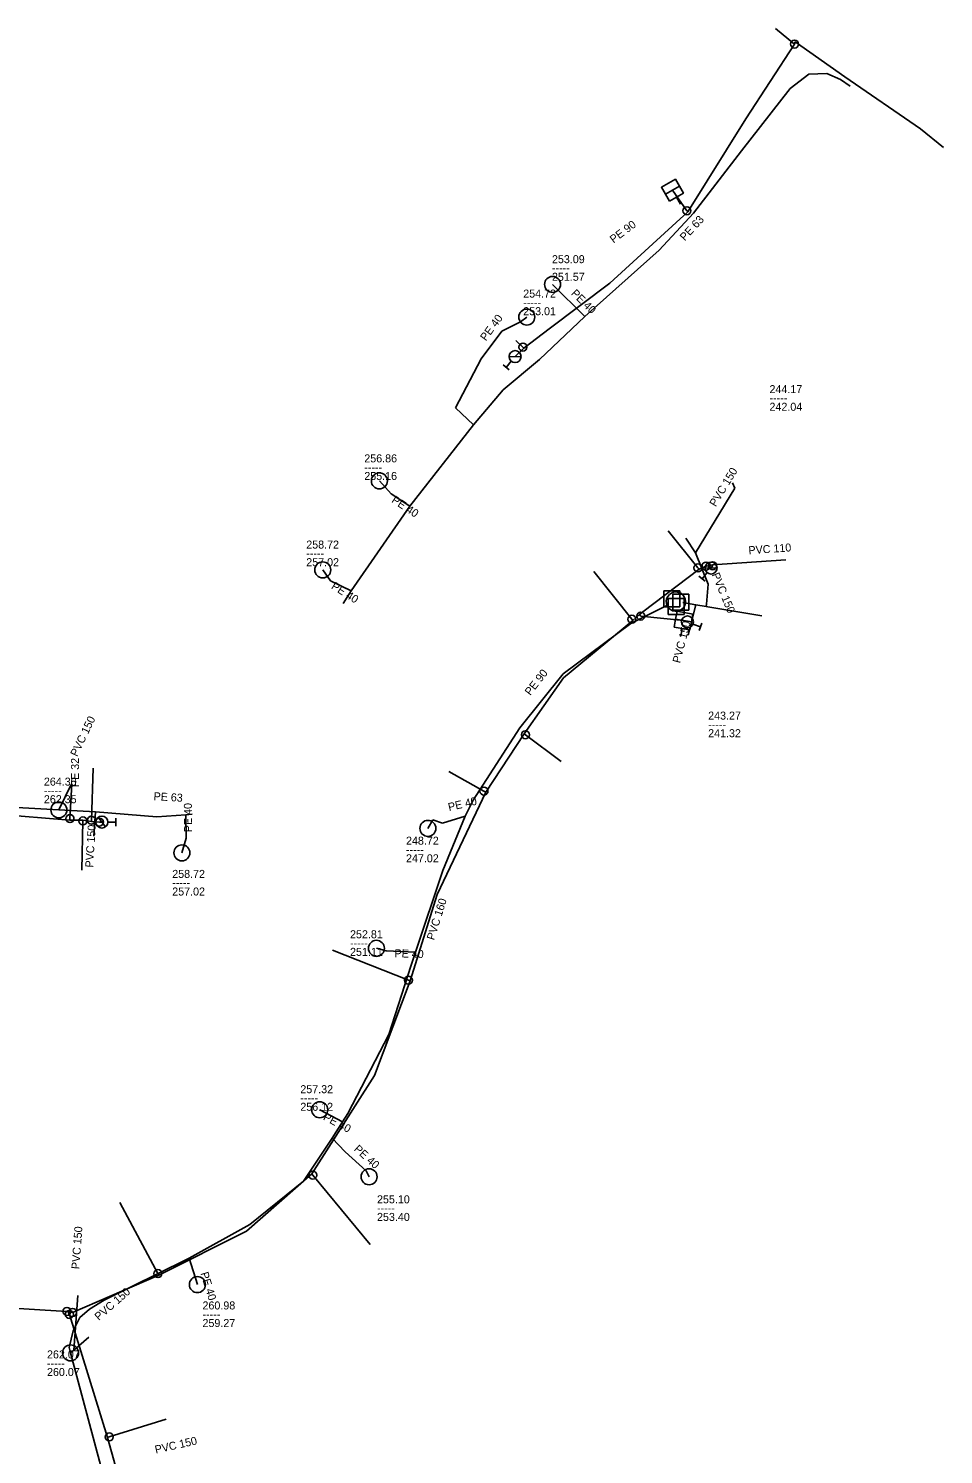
# Model space of a CAD drawing. Extents: x -770828 to -770111, y -1050344 to -1049447.
# Drawn here: x -770489.8 to -770375.5, y -1049916.1 to -1049737.9 of the extents above; entities that cross this region are included whole.
import ezdxf

# ---------------------------------------------------------------- set-up
doc = ezdxf.new("R2010")
doc.units = 0
doc.layers.add('Level 0', color=7, linetype='Continuous')

msp = doc.modelspace()

# ---------------------------------------------------------------- linework, layer by layer
at = {"layer": 'Level 0'}
for p, q in [((-770394.14, -1049739.85), (-770396.52, -1049737.91)), ((-770394.06, -1049739.59), (-770394.14, -1049739.85)), ((-770387.88, -1049743.95), (-770394.06, -1049739.59)), ((-770394.14, -1049739.85), (-770400.21, -1049749.18)), ((-770394.67, -1049745.42), (-770392.36, -1049743.62)), ((-770392.36, -1049743.62), (-770390.11, -1049743.54)), ((-770390.11, -1049743.54), (-770388.42, -1049744.28)), ((-770388.42, -1049744.28), (-770387.18, -1049745.13)), ((-770378.39, -1049750.44), (-770387.88, -1049743.95)), ((-770400.76, -1049753.2), (-770394.67, -1049745.42)), ((-770400.21, -1049749.18), (-770407.46, -1049760.81)), ((-770375.54, -1049752.77), (-770378.39, -1049750.44)), ((-770406.77, -1049760.98), (-770400.76, -1049753.2)), ((-770407.59, -1049760.68), (-770409.39, -1049758.11)), ((-770408.39, -1049759.84), (-770408.89, -1049758.98)), ((-770407.46, -1049760.81), (-770417.2, -1049769.74)), ((-770411.04, -1049765.6), (-770406.77, -1049760.98)), ((-770407.46, -1049760.81), (-770407.59, -1049760.68)), ((-770420.32, -1049773.89), (-770411.04, -1049765.6)), ((-770417.2, -1049769.74), (-770424.81, -1049775.44)), ((-770424.37, -1049769.88), (-770420.32, -1049773.89)), ((-770430.72, -1049775.71), (-770428.36, -1049774.58)), ((-770428.36, -1049774.58), (-770427.58, -1049773.96)), ((-770426.01, -1049779.27), (-770420.32, -1049773.89)), ((-770433.3, -1049779.19), (-770430.72, -1049775.71)), ((-770428.07, -1049777.72), (-770428.97, -1049776.89)), ((-770424.81, -1049775.44), (-770427.94, -1049777.86)), ((-770428.29, -1049778.93), (-770429.79, -1049778.88)), ((-770427.94, -1049777.86), (-770429.04, -1049778.91)), ((-770427.94, -1049777.86), (-770428.07, -1049777.72)), ((-770436.48, -1049785.3), (-770433.3, -1049779.19)), ((-770429.78, -1049780.57), (-770430.55, -1049779.93)), ((-770430.52, -1049783.05), (-770426.01, -1049779.27)), ((-770429.52, -1049779.48), (-770430.16, -1049780.25)), ((-770434.26, -1049787.42), (-770430.52, -1049783.05)), ((-770434.26, -1049787.42), (-770436.48, -1049785.3)), ((-770442.2, -1049797.59), (-770434.26, -1049787.42)), ((-770446, -1049794.44), (-770444.53, -1049796.05)), ((-770401.89, -1049794.68), (-770401.6, -1049795.33)), ((-770444.53, -1049796.05), (-770442.2, -1049797.59)), ((-770401.6, -1049795.33), (-770406.51, -1049803.42)), ((-770449.51, -1049808.19), (-770442.2, -1049797.59)), ((-770406.2, -1049805.3), (-770409.92, -1049800.66)), ((-770407.72, -1049801.61), (-770406.51, -1049803.42)), ((-770406.51, -1049803.42), (-770404.93, -1049807.33)), ((-770452.12, -1049806.93), (-770453.07, -1049805.56)), ((-770413.08, -1049810.8), (-770406.07, -1049805.46)), ((-770406.07, -1049805.46), (-770406.2, -1049805.3)), ((-770406.07, -1049805.46), (-770405.2, -1049805.08)), ((-770403.82, -1049805.34), (-770405.32, -1049805.29)), ((-770405.2, -1049805.08), (-770404.37, -1049804.93)), ((-770404.57, -1049805.32), (-770404.37, -1049805.03)), ((-770404.37, -1049804.93), (-770395.21, -1049804.29)), ((-770404.37, -1049805.03), (-770404.37, -1049804.93)), ((-770449.51, -1049808.19), (-770452.12, -1049806.93)), ((-770414.46, -1049811.72), (-770419.21, -1049805.74)), ((-770405.31, -1049806.98), (-770406.08, -1049806.34)), ((-770405.05, -1049805.89), (-770405.69, -1049806.66)), ((-770404.93, -1049807.33), (-770405.12, -1049809.84)), ((-770450.52, -1049809.77), (-770449.51, -1049808.19)), ((-770408.47, -1049808.17), (-770410.47, -1049808.17)), ((-770410.47, -1049808.17), (-770410.47, -1049810.17)), ((-770410.12, -1049809.15), (-770410.17, -1049809.45)), ((-770409.98, -1049808.87), (-770410.12, -1049809.15)), ((-770409.78, -1049808.63), (-770409.98, -1049808.87)), ((-770407.91, -1049809.14), (-770409.91, -1049809.14)), ((-770409.91, -1049809.14), (-770409.91, -1049811.14)), ((-770409.53, -1049808.45), (-770409.78, -1049808.63)), ((-770409.24, -1049808.34), (-770409.53, -1049808.45)), ((-770407.33, -1049808.57), (-770409.33, -1049808.57)), ((-770409.33, -1049808.57), (-770409.33, -1049810.57)), ((-770408.93, -1049808.31), (-770409.24, -1049808.34)), ((-770408.62, -1049808.36), (-770408.93, -1049808.31)), ((-770408.34, -1049808.48), (-770408.62, -1049808.36)), ((-770408.47, -1049810.17), (-770408.47, -1049808.17)), ((-770408.09, -1049808.68), (-770408.34, -1049808.48)), ((-770407.91, -1049808.93), (-770408.09, -1049808.68)), ((-770407.79, -1049809.21), (-770407.91, -1049808.93)), ((-770407.91, -1049811.14), (-770407.91, -1049809.14)), ((-770407.75, -1049809.52), (-770407.79, -1049809.21)), ((-770407.33, -1049810.57), (-770407.33, -1049808.57)), ((-770410.01, -1049809.95), (-770414.59, -1049812.24)), ((-770413.5, -1049811.14), (-770413.08, -1049810.8)), ((-770410.47, -1049810.17), (-770408.47, -1049810.17)), ((-770410.17, -1049809.45), (-770410.15, -1049809.76)), ((-770410.15, -1049809.76), (-770410.05, -1049810.06)), ((-770410.05, -1049810.06), (-770409.88, -1049810.32)), ((-770409.88, -1049810.32), (-770409.65, -1049810.52)), ((-770409.65, -1049810.52), (-770409.37, -1049810.66)), ((-770409.37, -1049810.66), (-770409.07, -1049810.73)), ((-770409.33, -1049810.57), (-770407.33, -1049810.57)), ((-770409.07, -1049810.73), (-770408.76, -1049810.72)), ((-770408.76, -1049810.72), (-770408.46, -1049810.63)), ((-770408.46, -1049810.63), (-770408.2, -1049810.46)), ((-770408.2, -1049810.46), (-770407.98, -1049810.24)), ((-770406.45, -1049809.9), (-770408.11, -1049809.62)), ((-770407.98, -1049810.24), (-770407.83, -1049809.97)), ((-770407.83, -1049809.97), (-770407.76, -1049809.66)), ((-770407.76, -1049809.66), (-770407.75, -1049809.52)), ((-770406.45, -1049809.9), (-770407.43, -1049813.71)), ((-770405.17, -1049810.12), (-770406.45, -1049809.9)), ((-770405.12, -1049809.84), (-770405.17, -1049810.12)), ((-770404.99, -1049810.15), (-770405.17, -1049810.12)), ((-770399.49, -1049811.07), (-770404.99, -1049810.15)), ((-770414.59, -1049812.24), (-770423.06, -1049818.54)), ((-770423.01, -1049819.03), (-770414.35, -1049811.86)), ((-770414.35, -1049811.86), (-770414.46, -1049811.72)), ((-770414.35, -1049811.86), (-770413.5, -1049811.14)), ((-770413.5, -1049811.14), (-770413.34, -1049811.33)), ((-770413.34, -1049811.33), (-770408.01, -1049811.88)), ((-770409.91, -1049811.14), (-770407.91, -1049811.14)), ((-770408.01, -1049811.88), (-770407.53, -1049812.06)), ((-770406.83, -1049812.32), (-770405.89, -1049812.66)), ((-770405.71, -1049812.19), (-770406.06, -1049813.13)), ((-770398.24, -1049811.28), (-770399.49, -1049811.07)), ((-770408.36, -1049813.85), (-770408.18, -1049812.86)), ((-770423.06, -1049818.54), (-770428.44, -1049825.28)), ((-770427.93, -1049826.03), (-770423.01, -1049819.03)), ((-770428.44, -1049825.28), (-770434.27, -1049834.33)), ((-770432.71, -1049833.32), (-770427.93, -1049826.03)), ((-770427.93, -1049826.03), (-770427.76, -1049826.16)), ((-770427.76, -1049826.16), (-770423.3, -1049829.49)), ((-770481.96, -1049836.83), (-770481.76, -1049830.32)), ((-770486.03, -1049835.55), (-770484.49, -1049832.35)), ((-770484.39, -1049832.32), (-770484.64, -1049836.63)), ((-770432.93, -1049833.2), (-770437.32, -1049830.74)), ((-770438.77, -1049846.13), (-770432.71, -1049833.32)), ((-770432.71, -1049833.32), (-770432.93, -1049833.2)), ((-770484.64, -1049836.81), (-770495.51, -1049835.93)), ((-770486.03, -1049835.55), (-770493.55, -1049835.13)), ((-770481.46, -1049835.77), (-770486.03, -1049835.55)), ((-770481.46, -1049835.77), (-770481.65, -1049838.82)), ((-770473.8, -1049836.43), (-770481.46, -1049835.77)), ((-770434.27, -1049834.33), (-770435.27, -1049836.31)), ((-770484.64, -1049836.63), (-770484.64, -1049836.81)), ((-770483.03, -1049836.82), (-770484.64, -1049836.81)), ((-770483.03, -1049836.92), (-770483.17, -1049843.08)), ((-770483.03, -1049836.82), (-770483.03, -1049836.92)), ((-770481.97, -1049836.98), (-770483.03, -1049836.82)), ((-770481.97, -1049836.98), (-770481.96, -1049836.83)), ((-770480.97, -1049837.06), (-770481.97, -1049836.98)), ((-770481.12, -1049836.47), (-770480.2, -1049837.65)), ((-770480.66, -1049837.06), (-770480.97, -1049837.06)), ((-770479.91, -1049837.06), (-770478.91, -1049837.06)), ((-770478.91, -1049836.56), (-770478.91, -1049837.56)), ((-770470.18, -1049836.18), (-770473.8, -1049836.43)), ((-770469.39, -1049836.08), (-770470.18, -1049836.18)), ((-770470.18, -1049836.18), (-770470.11, -1049839.06)), ((-770439.32, -1049836.8), (-770439.94, -1049837.85)), ((-770438.12, -1049837.22), (-770439.32, -1049836.8)), ((-770435.27, -1049836.31), (-770438.12, -1049837.22)), ((-770435.27, -1049836.31), (-770438.07, -1049843.1)), ((-770470.11, -1049839.06), (-770470.66, -1049840.91)), ((-770438.07, -1049843.1), (-770441.48, -1049853.33)), ((-770442.14, -1049856.91), (-770438.77, -1049846.13)), ((-770442.37, -1049856.82), (-770451.85, -1049853.06)), ((-770445.15, -1049853.15), (-770446.37, -1049852.84)), ((-770441.48, -1049853.33), (-770445.15, -1049853.15)), ((-770441.48, -1049853.33), (-770442.02, -1049854.95)), ((-770442.02, -1049854.95), (-770444.82, -1049863.62)), ((-770446.59, -1049868.74), (-770442.14, -1049856.91)), ((-770442.14, -1049856.91), (-770442.37, -1049856.82)), ((-770444.82, -1049863.62), (-770449.93, -1049873.46)), ((-770454.43, -1049881.03), (-770446.59, -1049868.74)), ((-770450.6, -1049874.53), (-770453.45, -1049873.01)), ((-770450.6, -1049874.53), (-770451.91, -1049876.55)), ((-770449.93, -1049873.46), (-770450.6, -1049874.53)), ((-770451.91, -1049876.55), (-770455.49, -1049881.93)), ((-770451.91, -1049876.55), (-770450.27, -1049878.28)), ((-770450.27, -1049878.28), (-770447.64, -1049880.66)), ((-770462.59, -1049888.16), (-770454.43, -1049881.03)), ((-770455.49, -1049881.93), (-770462.18, -1049887.36)), ((-770454.43, -1049881.03), (-770454.31, -1049881.18)), ((-770454.31, -1049881.18), (-770447.13, -1049889.83)), ((-770447.64, -1049880.66), (-770447.28, -1049881.38)), ((-770473.66, -1049893.48), (-770478.43, -1049884.58)), ((-770462.18, -1049887.36), (-770469.74, -1049891.54)), ((-770473.56, -1049893.67), (-770462.59, -1049888.16)), ((-770470.1, -1049891.73), (-770480.37, -1049896.79)), ((-770469.74, -1049891.54), (-770470.1, -1049891.73)), ((-770469.74, -1049891.54), (-770468.73, -1049894.86)), ((-770484.32, -1049898.34), (-770473.56, -1049893.67)), ((-770473.56, -1049893.67), (-770473.66, -1049893.48)), ((-770484.18, -1049903.05), (-770483.68, -1049896.23)), ((-770496.01, -1049897.54), (-770485.03, -1049898.21)), ((-770485.03, -1049898.21), (-770484.67, -1049898.28)), ((-770484.67, -1049898.28), (-770484.72, -1049898.59)), ((-770484.67, -1049898.28), (-770484.32, -1049898.34)), ((-770482.22, -1049897.93), (-770483.41, -1049898.97)), ((-770480.37, -1049896.79), (-770482.22, -1049897.93)), ((-770484.72, -1049898.59), (-770479.95, -1049913.96)), ((-770483.41, -1049898.97), (-770484.26, -1049900.63)), ((-770484.26, -1049900.63), (-770484.76, -1049902.73)), ((-770484.18, -1049903.05), (-770482.3, -1049901.41)), ((-770484.76, -1049902.73), (-770484.57, -1049903.39)), ((-770484.57, -1049903.39), (-770484.18, -1049903.05)), ((-770484.57, -1049903.39), (-770480.8, -1049917.54)), ((-770479.73, -1049913.89), (-770472.62, -1049911.69)), ((-770479.95, -1049913.96), (-770479.73, -1049913.89)), ((-770479.95, -1049913.96), (-770476.22, -1049927.41))]:
    msp.add_line(p, q, dxfattribs=at)
for points in [[(-770410.26, -1049758.61), (-770410.76, -1049757.74), (-770409.02, -1049756.74), (-770408.52, -1049757.61)], [(-770408.99, -1049811.71), (-770408.82, -1049810.72), (-770406.85, -1049811.07), (-770407.03, -1049812.05)]]:
    msp.add_lwpolyline(points, dxfattribs=at)
for points in [[(-770409.76, -1049759.48), (-770408.02, -1049758.48), (-770408.52, -1049757.61), (-770410.26, -1049758.61)], [(-770409.17, -1049812.69), (-770407.2, -1049813.04), (-770407.03, -1049812.05), (-770408.99, -1049811.71)]]:
    msp.add_lwpolyline(points, close=True, dxfattribs=at)
for centre, radius in [((-770394.14, -1049739.85), 0.5), ((-770407.59, -1049760.68), 0.5), ((-770424.37, -1049769.88), 1), ((-770427.58, -1049773.96), 1), ((-770429.04, -1049778.91), 0.75), ((-770428.07, -1049777.72), 0.5), ((-770446, -1049794.44), 1), ((-770453.07, -1049805.56), 1), ((-770406.2, -1049805.3), 0.5), ((-770405.2, -1049805.08), 0.5), ((-770404.57, -1049805.32), 0.75), ((-770404.37, -1049805.03), 0.5), ((-770413.34, -1049811.33), 0.5), ((-770414.46, -1049811.72), 0.5), ((-770407.53, -1049812.06), 0.75), ((-770427.76, -1049826.16), 0.5), ((-770432.93, -1049833.2), 0.5), ((-770486.03, -1049835.55), 1), ((-770484.64, -1049836.63), 0.5), ((-770483.03, -1049836.92), 0.5), ((-770481.96, -1049836.83), 0.5), ((-770480.97, -1049837.06), 0.5), ((-770480.66, -1049837.06), 0.75), ((-770439.94, -1049837.85), 1), ((-770470.66, -1049840.91), 1), ((-770446.37, -1049852.84), 1), ((-770442.37, -1049856.82), 0.5), ((-770453.45, -1049873.01), 1), ((-770447.28, -1049881.38), 1), ((-770454.31, -1049881.18), 0.5), ((-770473.66, -1049893.48), 0.5), ((-770468.73, -1049894.86), 1), ((-770485.03, -1049898.21), 0.5), ((-770484.72, -1049898.59), 0.5), ((-770484.32, -1049898.34), 0.5), ((-770484.57, -1049903.39), 1), ((-770479.73, -1049913.89), 0.5)]:
    msp.add_circle(centre, radius, dxfattribs=at)

# ---------------------------------------------------------------- texts
for s, rotation, p in [('PE 90', 36.834, (-770416.75, -1049764.78)), ('PE 63', 47.255, (-770407.84, -1049764.52)), ('PE 40', 315.284, (-770422.12, -1049771.09)), ('PE 40', 53.448, (-770432.69, -1049777.03)), ('PVC 150', 58.746, (-770403.99, -1049797.74)), ('PE 40', 326.538, (-770444.56, -1049797.05)), ('PVC 110', 3.997, (-770399.86, -1049803.61)), ('PE 40', 327.642, (-770452.09, -1049807.83)), ('PVC 150', 292.578, (-770404.5, -1049806.14)), ('PVC 150', 75.575, (-770408.44, -1049817.27)), ('PE 90', 51.975, (-770427.14, -1049821.33)), ('PVC 150', 64.301, (-770483.75, -1049828.96)), ('PE 32', 90, (-770483.51, -1049832.69)), ('PE 63', 356.592, (-770474.22, -1049834.32)), ('PE 40', 13.073, (-770437.29, -1049835.7)), ('PE 40', 90.612, (-770469.38, -1049838.32)), ('PVC 150', 86.435, (-770481.75, -1049842.77)), ('PVC 160', 72.64, (-770439.16, -1049851.89)), ('PE 40', 358.275, (-770444.12, -1049853.95)), ('PE 40', 331.928, (-770453.1, -1049874.21)), ('PE 40', 317.857, (-770449.25, -1049878.03)), ('PVC 150', 85.807, (-770483.47, -1049892.96)), ('PE 40', 286.921, (-770468.35, -1049893.44)), ('PVC 150', 41.1, (-770481.04, -1049899.41)), ('PVC 150', 12.645, (-770473.92, -1049915.98))]:
    msp.add_text(s, height=1, rotation=rotation, dxfattribs=at).set_placement(p)
for s, p in [('253.09', (-770424.44, -1049767.23)), ('-----', (-770424.44, -1049768.33)), ('251.57', (-770424.44, -1049769.43)), ('254.72', (-770428.03, -1049771.53)), ('-----', (-770428.03, -1049772.63)), ('253.01', (-770428.03, -1049773.73)), ('244.17', (-770397.27, -1049783.47)), ('-----', (-770397.27, -1049784.57)), ('242.04', (-770397.27, -1049785.67)), ('256.86', (-770447.88, -1049792.12)), ('-----', (-770447.88, -1049793.22)), ('255.16', (-770447.88, -1049794.32)), ('258.72', (-770455.13, -1049802.89)), ('-----', (-770455.13, -1049803.99)), ('257.02', (-770455.13, -1049805.09)), ('243.27', (-770404.93, -1049824.26)), ('-----', (-770404.93, -1049825.36)), ('241.32', (-770404.93, -1049826.46)), ('264.30', (-770487.9, -1049832.51)), ('-----', (-770487.9, -1049833.61)), ('262.35', (-770487.9, -1049834.71)), ('248.72', (-770442.67, -1049839.89)), ('-----', (-770442.67, -1049840.99)), ('247.02', (-770442.67, -1049842.09)), ('258.72', (-770471.87, -1049844.04)), ('-----', (-770471.87, -1049845.14)), ('257.02', (-770471.87, -1049846.24)), ('252.81', (-770449.66, -1049851.58)), ('-----', (-770449.66, -1049852.68)), ('251.11', (-770449.66, -1049853.78)), ('-----', (-770455.87, -1049872.04)), ('257.32', (-770455.87, -1049870.94)), ('256.12', (-770455.87, -1049873.14)), ('255.10', (-770446.29, -1049884.7)), ('-----', (-770446.29, -1049885.8)), ('253.40', (-770446.29, -1049886.9)), ('260.98', (-770468.09, -1049897.96)), ('-----', (-770468.09, -1049899.06)), ('259.27', (-770468.09, -1049900.16)), ('262.07', (-770487.51, -1049904.08)), ('-----', (-770487.51, -1049905.18)), ('260.07', (-770487.51, -1049906.28))]:
    msp.add_text(s, height=1, dxfattribs=at).set_placement(p)

doc.saveas('drawing.dxf')
